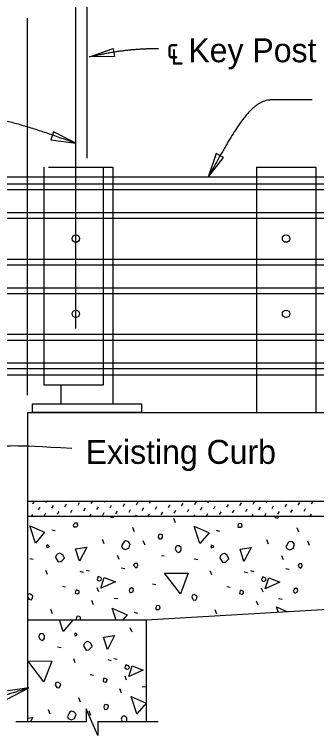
# Model space of a CAD drawing. Extents: x 21526.6 to 21595.9, y 56117 to 56157.3.
# Drawn here: x 21554.19 to 21556.74, y 56132.49 to 56138.56 of the extents above; entities that cross this region are included whole.
import ezdxf

# ---------------------------------------------------------------- set-up
doc = ezdxf.new("R2010")
doc.units = 0
for name, color, linetype in [('AdhocPoint_dp', 7, 'Continuous'), ('Border', 7, 'Continuous'), ('Patterning', 7, 'Continuous'), ('PlotBorder_dp', 7, 'Continuous'), ('SheetBorder_dp', 7, 'Continuous')]:
    doc.layers.add(name, color=color, linetype=linetype)

msp = doc.modelspace()

# ---------------------------------------------------------------- linework, layer by layer
at = {"layer": 'AdhocPoint_dp'}
for p, q in [((21554.3017, 56135.21), (21555.3017, 56135.21)), ((21554.3018, 56135.2101), (21554.3018, 56132.6054)), ((21554.3018, 56135.21), (21562.4118, 56135.21)), ((21565.8764, 56134.4601), (21554.3018, 56134.4601)), ((21554.3018, 56134.3351), (21565.8764, 56134.3351)), ((21559.5217, 56133.71), (21555.3017, 56133.4601)), ((21555.3017, 56133.46), (21554.3017, 56133.46)), ((21555.3017, 56133.4601), (21555.3017, 56132.6054))]:
    msp.add_line(p, q, dxfattribs=at)
at = {"layer": 'Patterning'}
for p, q in [((21554.7081, 56135.9163), (21554.7081, 56138.7275)), ((21554.8018, 56138.7275), (21554.8018, 56137.3509)), ((21554.4372, 56137.2725), (21554.4372, 56135.4392)), ((21554.479, 56137.2725), (21555.0205, 56137.2725)), ((21554.9372, 56137.2725), (21554.9372, 56135.4392)), ((21556.2288, 56137.2725), (21556.2288, 56135.21)), ((21556.2288, 56137.2725), (21556.7288, 56137.2725)), ((21556.7288, 56137.2725), (21556.7288, 56135.21)), ((21552.8484, 56137.1336), (21564.1633, 56137.1336)), ((21552.8484, 56137.0853), (21564.1633, 56137.0853)), ((21552.8484, 56136.8925), (21564.1633, 56136.8925)), ((21552.8484, 56136.8443), (21564.1633, 56136.8443)), ((21552.8484, 56136.5003), (21564.1633, 56136.5003)), ((21552.8484, 56136.4521), (21564.1633, 56136.4521)), ((21552.8484, 56136.2593), (21564.1633, 56136.2593)), ((21552.8484, 56136.2112), (21564.1633, 56136.2112)), ((21552.8484, 56135.8672), (21564.1633, 56135.8672)), ((21552.8484, 56135.819), (21564.1633, 56135.819)), ((21552.8484, 56135.6262), (21564.1633, 56135.6262)), ((21552.8484, 56135.5779), (21564.1633, 56135.5779)), ((21554.3461, 56134.4388), (21554.3585, 56134.4601)), ((21554.4568, 56134.4517), (21554.4616, 56134.4601)), ((21554.5056, 56134.4029), (21554.5186, 56134.4253)), ((21554.6162, 56134.4159), (21554.6292, 56134.4383)), ((21554.7269, 56134.4288), (21554.7398, 56134.4512)), ((21554.8375, 56134.4418), (21554.8481, 56134.4601)), ((21554.9481, 56134.4548), (21554.9512, 56134.4601)), ((21554.997, 56134.4059), (21555.0099, 56134.4283)), ((21555.1076, 56134.4189), (21555.1206, 56134.4413)), ((21555.2182, 56134.4319), (21555.2312, 56134.4542)), ((21555.3289, 56134.4448), (21555.3377, 56134.4601)), ((21555.4395, 56134.4578), (21555.4409, 56134.4601)), ((21555.4883, 56134.4089), (21555.5013, 56134.4313)), ((21555.599, 56134.4219), (21555.6119, 56134.4443)), ((21555.7096, 56134.4349), (21555.7226, 56134.4573)), ((21555.8202, 56134.4478), (21555.8273, 56134.4601)), ((21555.8691, 56134.399), (21555.882, 56134.4214)), ((21555.9797, 56134.412), (21555.9927, 56134.4344)), ((21556.0903, 56134.4249), (21556.1033, 56134.4473)), ((21556.201, 56134.4379), (21556.2138, 56134.4601)), ((21556.3116, 56134.4509), (21556.317, 56134.4601)), ((21556.3604, 56134.402), (21556.3734, 56134.4244)), ((21556.4711, 56134.415), (21556.484, 56134.4374)), ((21556.5817, 56134.428), (21556.5947, 56134.4503)), ((21556.6923, 56134.4409), (21556.7035, 56134.4601)), ((21554.395, 56134.3899), (21554.4079, 56134.4123)), ((21554.4438, 56134.3411), (21554.4568, 56134.3635)), ((21554.5544, 56134.3541), (21554.5674, 56134.3765)), ((21554.6651, 56134.367), (21554.678, 56134.3894)), ((21554.7757, 56134.38), (21554.7887, 56134.4024)), ((21554.8863, 56134.393), (21554.8993, 56134.4154)), ((21554.9352, 56134.3441), (21554.9481, 56134.3665)), ((21555.0458, 56134.3571), (21555.0588, 56134.3795)), ((21555.1564, 56134.3701), (21555.1694, 56134.3925)), ((21555.2671, 56134.383), (21555.28, 56134.4054)), ((21555.3777, 56134.396), (21555.3907, 56134.4184)), ((21555.4265, 56134.3472), (21555.4395, 56134.3695)), ((21555.5372, 56134.3601), (21555.5501, 56134.3825)), ((21555.6478, 56134.3731), (21555.6608, 56134.3955)), ((21555.7584, 56134.386), (21555.7714, 56134.4084)), ((21555.9179, 56134.3502), (21555.9309, 56134.3726)), ((21556.0285, 56134.3631), (21556.0415, 56134.3855)), ((21556.1392, 56134.3761), (21556.1521, 56134.3985)), ((21556.2498, 56134.3891), (21556.2628, 56134.4115)), ((21556.2986, 56134.3402), (21556.3116, 56134.3626)), ((21556.4093, 56134.3532), (21556.4222, 56134.3756)), ((21556.5199, 56134.3662), (21556.5329, 56134.3885)), ((21556.6305, 56134.3791), (21556.6435, 56134.4015)), ((21554.3372, 56134.3351), (21554.3461, 56134.3505)), ((21554.7237, 56134.3351), (21554.7269, 56134.3406)), ((21554.8268, 56134.3351), (21554.8375, 56134.3536)), ((21555.2133, 56134.3351), (21555.2182, 56134.3436)), ((21555.3164, 56134.3351), (21555.3289, 56134.3566)), ((21555.5488, 56134.2802), (21555.5346, 56134.3156)), ((21555.7029, 56134.3351), (21555.7096, 56134.3466)), ((21555.7313, 56134.3351), (21555.7532, 56134.3326)), ((21555.8073, 56134.3372), (21555.8202, 56134.3596)), ((21556.0894, 56134.3351), (21556.0903, 56134.3367)), ((21556.1925, 56134.3351), (21556.201, 56134.3497)), ((21556.579, 56134.3351), (21556.5817, 56134.3397)), ((21556.6821, 56134.3351), (21556.6923, 56134.3527)), ((21555.2029, 56134.2054), (21555.1888, 56134.2407)), ((21554.5046, 56134.2213), (21554.5329, 56134.2142)), ((21555.8893, 56134.2177), (21555.9176, 56134.2107)), ((21556.5876, 56134.2018), (21556.5734, 56134.2372)), ((21554.9466, 56134.1046), (21554.9324, 56134.1399)), ((21555.2907, 56134.0928), (21555.2765, 56134.1282)), ((21556.3313, 56134.1011), (21556.3171, 56134.1364)), ((21556.6753, 56134.0893), (21556.6612, 56134.1247)), ((21555.0721, 56133.972), (21555.0597, 56134.0056)), ((21555.4286, 56134.0045), (21555.4533, 56134.0009)), ((21556.4568, 56133.9685), (21556.4444, 56134.0021)), ((21554.3196, 56133.9797), (21554.3497, 56133.9744)), ((21555.7043, 56133.9762), (21555.7344, 56133.9709)), ((21554.4681, 56133.8454), (21554.4558, 56133.8789)), ((21554.7945, 56133.8819), (21554.8228, 56133.8748)), ((21555.0909, 56133.9002), (21555.121, 56133.8949)), ((21555.8528, 56133.8418), (21555.8404, 56133.8754)), ((21556.1792, 56133.8783), (21556.2075, 56133.8712)), ((21556.4756, 56133.8966), (21556.5056, 56133.8913)), ((21554.7421, 56133.8719), (21554.7704, 56133.8648)), ((21556.1268, 56133.8683), (21556.1551, 56133.8613)), ((21555.3543, 56133.7676), (21555.3808, 56133.7623)), ((21554.5954, 56133.7464), (21554.6219, 56133.7411)), ((21554.9006, 56133.6993), (21554.8882, 56133.7328)), ((21555.9801, 56133.7428), (21556.0066, 56133.7375)), ((21556.2853, 56133.6957), (21556.2729, 56133.7293)), ((21555.0308, 56133.6456), (21555.0626, 56133.6421)), ((21556.4155, 56133.6421), (21556.4473, 56133.6385)), ((21554.8582, 56133.5897), (21554.844, 56133.625)), ((21556.2429, 56133.5861), (21556.2287, 56133.6215)), ((21554.5123, 56133.5148), (21554.4982, 56133.5501)), ((21555.1987, 56133.5272), (21555.227, 56133.5201)), ((21555.897, 56133.5112), (21555.8829, 56133.5466)), ((21555.1813, 56133.3611), (21555.1671, 56133.3965)), ((21554.3017, 56133.2612), (21554.3033, 56133.261)), ((21554.5543, 56133.2362), (21554.5844, 56133.2309)), ((21554.7028, 56133.1019), (21554.6905, 56133.1355)), ((21554.9768, 56133.1284), (21555.0051, 56133.1213)), ((21555.0292, 56133.1384), (21555.0575, 56133.1313)), ((21554.8301, 56133.0029), (21554.8566, 56132.9976)), ((21555.1353, 56132.9558), (21555.1229, 56132.9894)), ((21555.0929, 56132.8462), (21555.0787, 56132.8815)), ((21555.2655, 56132.9021), (21555.2973, 56132.8986)), ((21554.747, 56132.7713), (21554.7329, 56132.8067)), ((21554.4907, 56132.6706), (21554.4766, 56132.7059)), ((21554.8348, 56132.6588), (21554.8206, 56132.6942))]:
    msp.add_line(p, q, dxfattribs=at)
for points in [[(21554.9988, 56134.3351), (21555.0031, 56134.3273), (21555.0244, 56134.3238), (21555.0306, 56134.3351)], [(21556.3816, 56134.3351), (21556.3878, 56134.3238), (21556.409, 56134.3203), (21556.4173, 56134.3351)], [(21554.3674, 56134.1088), (21554.3196, 56134.2555), (21554.4452, 56134.2007), (21554.3674, 56134.1088)], [(21554.692, 56134.246), (21554.7132, 56134.246), (21554.7238, 56134.2566), (21554.7185, 56134.2761), (21554.6956, 56134.2778), (21554.692, 56134.2672), (21554.6867, 56134.2584), (21554.692, 56134.246), (21554.6885, 56134.2495)], [(21555.7521, 56134.1052), (21555.7043, 56134.2519), (21555.8298, 56134.1971), (21555.7521, 56134.1052)], [(21556.0767, 56134.2425), (21556.0979, 56134.2425), (21556.1085, 56134.2531), (21556.1032, 56134.2725), (21556.0802, 56134.2743), (21556.0767, 56134.2637), (21556.0714, 56134.2549), (21556.0767, 56134.2425), (21556.0732, 56134.246)], [(21555.4003, 56134.16), (21555.4091, 56134.1441), (21555.4286, 56134.1459), (21555.4374, 56134.1582), (21555.4392, 56134.1777), (21555.4268, 56134.183), (21555.4179, 56134.1848), (21555.4073, 56134.1812), (21555.4038, 56134.1777), (21555.4003, 56134.16)], [(21555.1004, 56134.0675), (21555.1234, 56134.0551), (21555.1534, 56134.0675), (21555.1658, 56134.1046), (21555.1481, 56134.1223), (21555.1251, 56134.1276), (21555.1145, 56134.1205), (21555.1021, 56134.1011), (21555.0933, 56134.0851), (21555.1004, 56134.0675)], [(21556.485, 56134.0639), (21556.508, 56134.0516), (21556.5381, 56134.0639), (21556.5505, 56134.1011), (21556.5328, 56134.1187), (21556.5098, 56134.124), (21556.4992, 56134.117), (21556.4868, 56134.0975), (21556.478, 56134.0816), (21556.485, 56134.0639)], [(21554.4664, 56134.0734), (21554.4858, 56134.0822), (21554.4787, 56134.0893), (21554.4664, 56134.0946), (21554.4611, 56134.0822), (21554.4664, 56134.0734)], [(21554.7397, 56133.9579), (21554.7062, 56134.0622), (21554.7999, 56134.0745), (21554.7397, 56133.9579)], [(21555.5452, 56134.061), (21555.5558, 56134.0398), (21555.5735, 56134.0292), (21555.5876, 56134.0398), (21555.5947, 56134.0504), (21555.5947, 56134.0716), (21555.5788, 56134.0875), (21555.5594, 56134.0858), (21555.5505, 56134.0769), (21555.5452, 56134.061)], [(21555.851, 56134.0699), (21555.8705, 56134.0787), (21555.8634, 56134.0858), (21555.851, 56134.0911), (21555.8457, 56134.0787), (21555.851, 56134.0699)], [(21556.1244, 56133.9543), (21556.0908, 56134.0586), (21556.1845, 56134.071), (21556.1244, 56133.9543)], [(21554.5371, 56133.9885), (21554.5601, 56133.9514), (21554.583, 56133.9532), (21554.5919, 56133.962), (21554.6113, 56133.9815), (21554.599, 56134.0115), (21554.5742, 56134.0257), (21554.5565, 56134.0186), (21554.5424, 56134.0045), (21554.5371, 56133.9885)], [(21555.9218, 56133.985), (21555.9447, 56133.9479), (21555.9677, 56133.9497), (21555.9766, 56133.9585), (21555.996, 56133.9779), (21555.9836, 56134.008), (21555.9589, 56134.0221), (21555.9412, 56134.0151), (21555.9271, 56134.0009), (21555.9218, 56133.985)], [(21555.2023, 56133.9125), (21555.2129, 56133.9019), (21555.2235, 56133.909), (21555.2306, 56133.9196), (21555.227, 56133.9373), (21555.2182, 56133.939), (21555.2058, 56133.9373), (21555.1952, 56133.9267), (21555.2023, 56133.9125)], [(21556.587, 56133.909), (21556.5976, 56133.8984), (21556.6082, 56133.9055), (21556.6152, 56133.9161), (21556.6117, 56133.9337), (21556.6029, 56133.9355), (21556.5905, 56133.9337), (21556.5799, 56133.9231), (21556.587, 56133.909)], [(21554.8971, 56133.7935), (21554.9095, 56133.7917), (21554.9218, 56133.797), (21554.9254, 56133.8076), (21554.9201, 56133.8164), (21554.9095, 56133.8235), (21554.8971, 56133.8288), (21554.89, 56133.8147), (21554.8865, 56133.8041), (21554.8971, 56133.7935)], [(21554.9194, 56133.7287), (21554.9477, 56133.8206), (21555.0414, 56133.7835), (21554.9194, 56133.7287)], [(21555.5894, 56133.681), (21555.4551, 56133.8577), (21555.6548, 56133.856), (21555.5894, 56133.681)], [(21556.2818, 56133.7899), (21556.2941, 56133.7882), (21556.3065, 56133.7935), (21556.31, 56133.8041), (21556.3047, 56133.8129), (21556.2941, 56133.82), (21556.2818, 56133.8253), (21556.2747, 56133.8111), (21556.2711, 56133.8005), (21556.2818, 56133.7899)], [(21556.3041, 56133.7251), (21556.3324, 56133.8171), (21556.4261, 56133.7799), (21556.3041, 56133.7251)], [(21554.7033, 56133.688), (21554.7227, 56133.6827), (21554.7351, 56133.6916), (21554.7368, 56133.7039), (21554.7333, 56133.7075), (21554.7192, 56133.7145), (21554.7068, 56133.7128), (21554.705, 56133.7004), (21554.7033, 56133.688)], [(21555.1669, 56133.6933), (21555.174, 56133.6933), (21555.1881, 56133.7004), (21555.1934, 56133.7163), (21555.1917, 56133.7251), (21555.1775, 56133.7322), (21555.1598, 56133.7216), (21555.1563, 56133.711), (21555.1598, 56133.7004), (21555.1669, 56133.6933)], [(21556.0879, 56133.6845), (21556.1074, 56133.6792), (21556.1197, 56133.688), (21556.1215, 56133.7004), (21556.118, 56133.7039), (21556.1038, 56133.711), (21556.0915, 56133.7092), (21556.0897, 56133.6969), (21556.0879, 56133.6845)], [(21556.5516, 56133.6898), (21556.5587, 56133.6898), (21556.5728, 56133.6969), (21556.5781, 56133.7128), (21556.5763, 56133.7216), (21556.5622, 56133.7287), (21556.5445, 56133.7181), (21556.541, 56133.7075), (21556.5445, 56133.6969), (21556.5516, 56133.6898)], [(21554.3037, 56133.6527), (21554.3126, 56133.6368), (21554.3338, 56133.6332), (21554.3426, 56133.6491), (21554.3462, 56133.6633), (21554.3373, 56133.6721), (21554.3214, 56133.681), (21554.3055, 56133.6756), (21554.3017, 56133.6643)], [(21554.3017, 56133.6567), (21554.3037, 56133.6527)], [(21555.6884, 56133.6491), (21555.6973, 56133.6332), (21555.7185, 56133.6297), (21555.7273, 56133.6456), (21555.7308, 56133.6597), (21555.722, 56133.6686), (21555.7061, 56133.6774), (21555.6902, 56133.6721), (21555.6849, 56133.6562), (21555.6884, 56133.6491)], [(21555.3861, 56133.5519), (21555.4073, 56133.5519), (21555.4179, 56133.5625), (21555.4126, 56133.582), (21555.3897, 56133.5837), (21555.3861, 56133.5731), (21555.3808, 56133.5643), (21555.3861, 56133.5519), (21555.3826, 56133.5554)], [(21556.4121, 56133.5297), (21556.3984, 56133.5719), (21556.4846, 56133.5343)], [(21555.0467, 56133.46), (21555.0138, 56133.5614), (21555.1393, 56133.5066), (21555.0999, 56133.46)], [(21554.6021, 56133.3653), (21554.5713, 56133.46)], [(21554.6734, 56133.46), (21554.6798, 56133.4572), (21554.6021, 56133.3653)], [(21554.7413, 56133.46), (21554.7468, 56133.4677), (21554.7486, 56133.4871), (21554.7362, 56133.4924), (21554.7274, 56133.4942), (21554.7168, 56133.4907), (21554.7132, 56133.4871), (21554.7097, 56133.4694)], [(21554.7097, 56133.4694), (21554.7149, 56133.46)], [(21554.3952, 56133.3211), (21554.4058, 56133.2999), (21554.4235, 56133.2893), (21554.4377, 56133.2999), (21554.4447, 56133.3105), (21554.4447, 56133.3317), (21554.4288, 56133.3476), (21554.4094, 56133.3458), (21554.4005, 56133.337), (21554.3952, 56133.3211)], [(21554.7011, 56133.3299), (21554.7205, 56133.3388), (21554.7134, 56133.3458), (21554.7011, 56133.3511), (21554.6958, 56133.3388), (21554.7011, 56133.3299)], [(21554.9744, 56133.2144), (21554.9409, 56133.3187), (21555.0345, 56133.3311), (21554.9744, 56133.2144)], [(21554.7718, 56133.2451), (21554.7948, 56133.208), (21554.8177, 56133.2097), (21554.8266, 56133.2186), (21554.846, 56133.238), (21554.8336, 56133.2681), (21554.8089, 56133.2822), (21554.7912, 56133.2751), (21554.7771, 56133.261), (21554.7718, 56133.2451)], [(21554.4394, 56132.941), (21554.3051, 56133.1178), (21554.5048, 56133.116), (21554.4394, 56132.941)], [(21555.1318, 56133.05), (21555.1441, 56133.0482), (21555.1565, 56133.0535), (21555.1601, 56133.0641), (21555.1548, 56133.073), (21555.1441, 56133.0801), (21555.1318, 56133.0854), (21555.1247, 56133.0712), (21555.1212, 56133.0606), (21555.1318, 56133.05)], [(21555.1541, 56132.9852), (21555.1824, 56133.0771), (21555.2761, 56133.04), (21555.1541, 56132.9852)], [(21554.9379, 56132.9446), (21554.9574, 56132.9393), (21554.9698, 56132.9481), (21554.9715, 56132.9605), (21554.968, 56132.964), (21554.9539, 56132.9711), (21554.9415, 56132.9693), (21554.9397, 56132.9569), (21554.9379, 56132.9446)], [(21554.5384, 56132.9092), (21554.5473, 56132.8933), (21554.5685, 56132.8898), (21554.5773, 56132.9057), (21554.5809, 56132.9198), (21554.572, 56132.9287), (21554.5561, 56132.9375), (21554.5402, 56132.9322), (21554.5349, 56132.9163), (21554.5384, 56132.9092)], [(21555.2222, 56132.6712), (21555.1745, 56132.8179), (21555.3, 56132.7631), (21555.2222, 56132.6712)], [(21554.9444, 56132.726), (21554.9532, 56132.7101), (21554.9727, 56132.7118), (21554.9815, 56132.7242), (21554.9833, 56132.7437), (21554.9709, 56132.749), (21554.9621, 56132.7507), (21554.9515, 56132.7472), (21554.9479, 56132.7437), (21554.9444, 56132.726)], [(21554.6445, 56132.6334), (21554.6675, 56132.6211), (21554.6975, 56132.6334), (21554.7099, 56132.6706), (21554.6922, 56132.6882), (21554.6692, 56132.6935), (21554.6586, 56132.6865), (21554.6463, 56132.667), (21554.6374, 56132.6511), (21554.6445, 56132.6334)], [(21554.3018, 56132.6349), (21554.344, 56132.6405), (21554.3259, 56132.6054)], [(21555.1313, 56132.6054), (21555.1318, 56132.6058), (21555.1388, 56132.6164), (21555.1388, 56132.6376), (21555.1229, 56132.6535), (21555.1035, 56132.6517), (21555.0946, 56132.6429), (21555.0893, 56132.627)], [(21555.0893, 56132.627), (21555.1, 56132.6058), (21555.1005, 56132.6054)]]:
    msp.add_lwpolyline(points, dxfattribs=at)
for centre in [(21554.7081, 56136.6724), (21554.7081, 56136.0393)]:
    msp.add_circle(centre, 0.0312, dxfattribs=at)
at = {"layer": 'PlotBorder_dp'}
msp.add_line((21554.3017, 56135.3555), (21554.3017, 56138.5276), dxfattribs=at)
for points in [[(21554.8226, 56138.2024), (21555.0213, 56138.2741), (21555.0338, 56138.2047)], [(21554.7081, 56137.4747), (21554.5204, 56137.5715), (21554.4989, 56137.5043)], [(21555.8233, 56137.1892), (21555.9529, 56137.356), (21555.8907, 56137.3893)], [(21554.3117, 56132.8915), (21554.1029, 56132.8596), (21554.1251, 56132.7926)]]:
    msp.add_lwpolyline(points, close=True, dxfattribs=at)
msp.add_lwpolyline([(21555.4017, 56132.6055), (21554.8932, 56132.6055), (21554.8932, 56132.4893), (21554.7938, 56132.7143), (21554.7938, 56132.6055), (21554.2018, 56132.6055)], dxfattribs=at)
for points, degree in [([(21554.8226, 56138.2028), (21555.1141, 56138.2737), (21555.4056, 56138.2737)], 2), ([(21556.6997, 56137.8396), (21556.4594, 56137.8396), (21556.2473, 56137.8396), (21556.0283, 56137.571), (21555.8233, 56137.1892)], 2), ([(21552.581, 56137.751), (21553.1726, 56137.7569), (21553.9973, 56137.7421), (21554.7081, 56137.4746)], 2), ([(21554.6745, 56134.9046), (21554.1531, 56134.9384), (21554.0496, 56134.9162), (21553.9557, 56134.8796), (21553.7845, 56134.6171)], 3), ([(21554.3117, 56132.8915), (21553.648, 56132.6719), (21553.044, 56132.6254)], 2)]:
    msp.add_open_spline(points, degree=degree, dxfattribs=at)
at = {"layer": 'SheetBorder_dp'}
for p, q in [((21555.0205, 56137.2725), (21555.0205, 56135.283)), ((21564.1633, 56137.1891), (21552.8484, 56137.1891)), ((21564.1633, 56135.5224), (21552.8484, 56135.5224)), ((21554.9372, 56135.4392), (21554.4372, 56135.4392)), ((21554.583, 56135.4392), (21554.583, 56135.283))]:
    msp.add_line(p, q, dxfattribs=at)
msp.add_lwpolyline([(21554.3434, 56135.21), (21554.3434, 56135.283), (21555.2601, 56135.283), (21555.2601, 56135.21)], close=True, dxfattribs=at)
for centre in [(21556.4788, 56136.6724), (21556.4788, 56136.0393)]:
    msp.add_circle(centre, 0.0312, dxfattribs=at)

# ---------------------------------------------------------------- texts
at = {"layer": 'Border'}
for s, p in [('℄ Key Post', (21555.4716, 56138.1571)), ('Existing Curb', (21554.7907, 56134.7766))]:
    msp.add_text(s, height=0.2016, dxfattribs=at).set_placement(p)

doc.saveas('drawing.dxf')
